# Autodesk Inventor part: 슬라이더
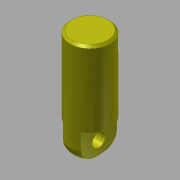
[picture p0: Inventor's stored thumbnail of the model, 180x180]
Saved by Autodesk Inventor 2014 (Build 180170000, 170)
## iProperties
Created: 2016-08
Part Number: 슬라이더
Material: 강철, 탄소
Document SubType Name: Modeling
Designer: mduedu
Density: 7.87 g/cm^3
Appearance: Yellow
Author: mduedu
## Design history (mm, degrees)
sketch "스케치1"
  geometry: C1 r 9 at (0, 0); 1 further point
  constraints: 1 centre point, 1 coincident
  dimensions: "d0" = 18 diameter of C1
extrude "돌출1" new body sketch "스케치1" distance "d1" = 47; taper "d2" = 0 deg
fillet "모깎기1" dims "d21" = 6
sketch "스케치6"
  geometry: L1 (9, 6)-(9, 47) reference; L2 (-9, 6)-(-9, 47) reference; L3 (9, 47)-(-9, 47) reference; L4 (0, 47)-(0, 0); L5 (9, 13)-(4, 13); L6 (4, 13)-(4, 0); L7 (4, 0)-(9, 0); L8 (9, 0)-(9, 13); L9 (-9, 13)-(-4, 13); L10 (-4, 13)-(-4, 0); L11 (-4, 0)-(-9, 0); L12 (-9, 0)-(-9, 13)
  constraints: 18 end point, 4 symmetric about line, 2 parallel, 2 perpendicular, 1 horizontal, 1 horizontal alignment, 1 midpoint, 1 point on line
  dimensions: "d22" = 13 distance of L7.end L5.start; "d24" = 4 distance between parallel lines of L6 L4
extrude "돌출5" cut sketch "스케치6" stored distance "d25" = 8; taper "d26" = 0 deg
sketch "스케치8"
  geometry: C1 r 3 at (6, 0); 1 further point
  constraints: 1 centre point, 1 horizontal alignment
  dimensions: "d27" = 6 diameter of C1; "d28" = 6 distance of point (0, 0) C1.centre
extrude "돌출6" cut sketch "스케치8" stored distance "d29" = 8; taper "d30" = 0 deg
chamfer "모따기2" distance "d43" = 1; stored, may be unused: second distance "d44" = 2, angle "d45" = 30 deg
node "솔리드1"
